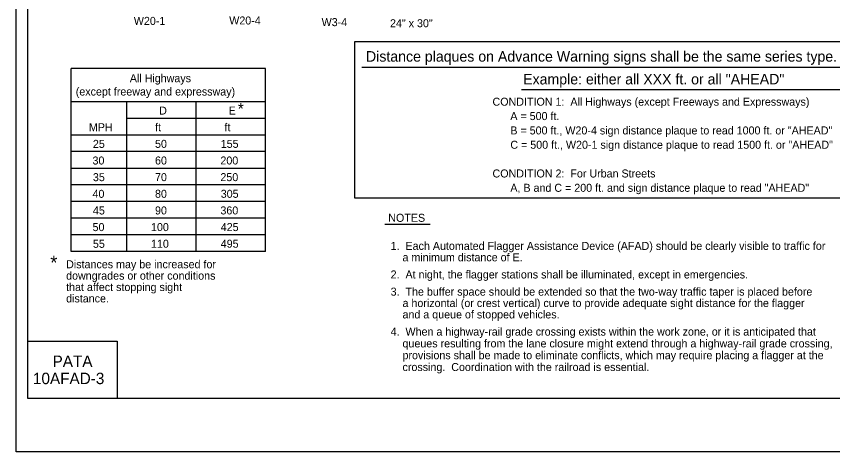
# Model space of a CAD drawing. Extents: x -14145 to -13521, y 30244 to 30661.
# Drawn here: x -13824.17 to -13802.75, y 30478.81 to 30490.24 of the extents above; entities that cross this region are included whole.
import ezdxf

# ---------------------------------------------------------------- set-up
doc = ezdxf.new("R2010")
doc.units = 0
for name, color, linetype in [('1', 7, 'Continuous'), ('10', 7, 'Continuous'), ('2', 7, 'Continuous'), ('3', 7, 'Continuous'), ('4', 7, 'Continuous'), ('5', 7, 'Continuous'), ('61', 7, 'Continuous')]:
    doc.layers.add(name, color=color, linetype=linetype)

msp = doc.modelspace()

# ---------------------------------------------------------------- linework, layer by layer
at = {"layer": '1'}
for p, q in [((-13822.732, 30484.06), (-13822.732, 30488.868)), ((-13817.632, 30488.868), (-13822.732, 30488.868)), ((-13817.632, 30484.06), (-13817.632, 30488.868)), ((-13817.632, 30487.994), (-13822.733, 30487.994)), ((-13821.275, 30484.06), (-13821.275, 30487.994)), ((-13819.453, 30484.06), (-13819.453, 30487.994)), ((-13817.632, 30487.557), (-13821.275, 30487.557)), ((-13817.632, 30487.12), (-13822.733, 30487.12)), ((-13817.632, 30486.683), (-13822.733, 30486.683)), ((-13817.632, 30486.245), (-13822.733, 30486.245)), ((-13817.632, 30485.808), (-13822.733, 30485.808)), ((-13817.632, 30485.371), (-13822.733, 30485.371)), ((-13817.632, 30484.934), (-13822.733, 30484.934)), ((-13817.632, 30484.497), (-13822.733, 30484.497)), ((-13817.632, 30484.06), (-13822.732, 30484.06))]:
    msp.add_line(p, q, dxfattribs=at)
at = {"layer": '10'}
for p, q in [((-13823.874, 30480.207), (-13823.874, 30502.777)), ((-13823.874, 30481.707), (-13821.524, 30481.707)), ((-13821.524, 30481.707), (-13821.524, 30480.207)), ((-13792.422, 30480.207), (-13823.874, 30480.207))]:
    msp.add_line(p, q, dxfattribs=at)
at = {"layer": '2'}
for p, q in [((-13815.103, 30488.901), (-13795.152, 30488.901)), ((-13810.916, 30488.316), (-13799.479, 30488.316)), ((-13813.31, 30484.77), (-13814.502, 30484.77))]:
    msp.add_line(p, q, dxfattribs=at)
at = {"layer": '5'}
msp.add_lwpolyline([(-13815.287, 30489.574), (-13794.9, 30489.574), (-13794.9, 30485.461), (-13815.287, 30485.461)], close=True, dxfattribs=at)
at = {"layer": '61'}
msp.add_lwpolyline([(-13824.174, 30504.307), (-13791.174, 30504.307), (-13791.174, 30478.807), (-13824.174, 30478.807)], close=True, dxfattribs=at)

# ---------------------------------------------------------------- texts
at = {"layer": '1'}
for s, p in [('CONDITION 1:  All Highways (except Freeways and Expressways)', (-13811.677, 30487.889)), ('      A = 500 ft.', (-13811.677, 30487.512)), ('      B = 500 ft., W20-4 sign distance plaque to read 1000 ft. or "AHEAD"', (-13811.677, 30487.135)), ('      C = 500 ft., W20-1 sign distance plaque to read 1500 ft. or "AHEAD"', (-13811.677, 30486.759)), ('CONDITION 2:  For Urban Streets', (-13811.677, 30486.005)), ('      A, B and C = 200 ft. and sign distance plaque to read "AHEAD"', (-13811.677, 30485.629))]:
    msp.add_text(s, height=0.21, dxfattribs=at).set_placement(p)
at = {"layer": '2'}
for s, height, p in [('W20-1', 0.21, (-13821.09, 30490.011)), ('W20-4', 0.21, (-13818.586, 30490.021)), ('W3-4', 0.21, (-13816.162, 30489.978)), ('24" x 30"', 0.21, (-13814.367, 30489.949)), ('Distance plaques on Advance Warning signs shall be the same series type.', 0.2772, (-13814.997, 30489.045)), ('Example: either all XXX ft. or all "AHEAD"', 0.2772, (-13810.873, 30488.448)), ('D', 0.21, (-13820.426, 30487.656)), ('E', 0.21, (-13818.602, 30487.656)), ('*', 0.302, (-13818.361, 30487.659)), ('MPH', 0.21, (-13822.269, 30487.219)), ('ft', 0.21, (-13820.533, 30487.219)), ('ft', 0.21, (-13818.711, 30487.219)), ('25', 0.21, (-13822.164, 30486.782)), ('50', 0.21, (-13820.534, 30486.783)), ('155', 0.21, (-13818.809, 30486.783)), ('30', 0.21, (-13822.174, 30486.345)), ('60', 0.21, (-13820.534, 30486.346)), ('200', 0.21, (-13818.818, 30486.346)), ('35', 0.21, (-13822.164, 30485.908)), ('70', 0.21, (-13820.534, 30485.909)), ('250', 0.21, (-13818.818, 30485.909)), ('40', 0.21, (-13822.174, 30485.471)), ('80', 0.21, (-13820.534, 30485.472)), ('305', 0.21, (-13818.809, 30485.472)), ('45', 0.21, (-13822.164, 30485.034)), ('90', 0.21, (-13820.534, 30485.035)), ('360', 0.21, (-13818.818, 30485.035)), ('NOTES', 0.21, (-13814.413, 30484.841)), ('50', 0.21, (-13822.173, 30484.597)), ('100', 0.21, (-13820.639, 30484.598)), ('425', 0.21, (-13818.809, 30484.598)), ('55', 0.21, (-13822.164, 30484.159)), ('110', 0.21, (-13820.639, 30484.161)), ('495', 0.21, (-13818.809, 30484.161)), ('1.  Each Automated Flagger Assistance Device (AFAD) should be clearly visible to traffic for ', 0.21, (-13814.351, 30484.104)), ('    a minimum distance of E.', 0.21, (-13814.351, 30483.805)), ('*', 0.363, (-13823.283, 30483.588)), ('Distances may be increased for ', 0.21, (-13822.867, 30483.622)), ('downgrades or other conditions ', 0.21, (-13822.867, 30483.323)), ('2.  At night, the flagger stations shall be illuminated, except in emergencies.', 0.21, (-13814.351, 30483.354)), ('that affect stopping sight ', 0.21, (-13822.867, 30483.024)), ('3.  The buffer space should be extended so that the two-way traffic taper is placed before ', 0.21, (-13814.351, 30482.903)), ('distance.', 0.21, (-13822.867, 30482.725)), ('    a horizontal (or crest vertical) curve to provide adequate sight distance for the flagger', 0.21, (-13814.351, 30482.604)), ('    and a queue of stopped vehicles.', 0.21, (-13814.351, 30482.305)), ('4.  When a highway-rail grade crossing exists within the work zone, or it is anticipated that ', 0.21, (-13814.351, 30481.854)), ('    queues resulting from the lane closure might extend through a highway-rail grade crossing, ', 0.21, (-13814.351, 30481.544)), ('    provisions shall be made to eliminate conflicts, which may require placing a flagger at the ', 0.21, (-13814.351, 30481.234)), ('    crossing.  Coordination with the railroad is essential.', 0.21, (-13814.351, 30480.924))]:
    msp.add_text(s, height=height, dxfattribs=at).set_placement(p)
at = {"layer": '3'}
msp.add_text('All Highways', height=0.20979, rotation=360, dxfattribs=at).set_placement((-13821.195, 30488.506))
msp.add_text('(except freeway and expressway)', height=0.21, dxfattribs=at).set_placement((-13822.614, 30488.156))
at = {"layer": '4'}
for s, p in [('PATA', (-13823.222, 30481.03)), ('10AFAD-3', (-13823.737, 30480.58))]:
    msp.add_text(s, height=0.3, dxfattribs=at).set_placement(p)

doc.saveas('drawing.dxf')
